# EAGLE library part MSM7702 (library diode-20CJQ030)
OKI's MSM7702-01/02/03 Single Rail CODEC Description: The MSM7702 is a single-channel CODEC CMOS IC for voice signals ranging from 300 to 3400 Hz with filters for A/D and D/A conversion. Designed especially for a single-power supply and low-power applications, the device is optimized for telephone terminals in digital wireless systems or ISDN systems. The MSM7702 utilizes low-voltage operational amplifiers (Op-amps) to provide low-power consumption. The device uses the same transmission clocks as those used in the MSM7508B and MSM7509B. The analog output signal can directly drive a piezoelectric type handset receiver. Features: Single power supply: +2.7 V to +3.8 V Low power consumption - Operating mode: 15 mW Typ. VDD = 3 V - Power save mode: 3.6 mW Typ. VDD = 3 V - Power down mode: 0.05 mW Typ. VDD = 3 V ITU-T Companding law - MSM7702-01: m/A-law pin selectable - MSM7702-02: m-law - MSM7702-03: A-law Built-in PLL eliminates a master clock Serial data rate: 64/128/256/512/1024/2048kHz 96/192/384/768/1536/1544/200 kHz Adjustable transmit gain Built-in reference voltage supply Analog output can directly drive a load equivalent to 1.2 kW Pin-for-pin compatible with the MSM7578 and MSM7579 Please send any comments to: messi@users.sourceforge.net
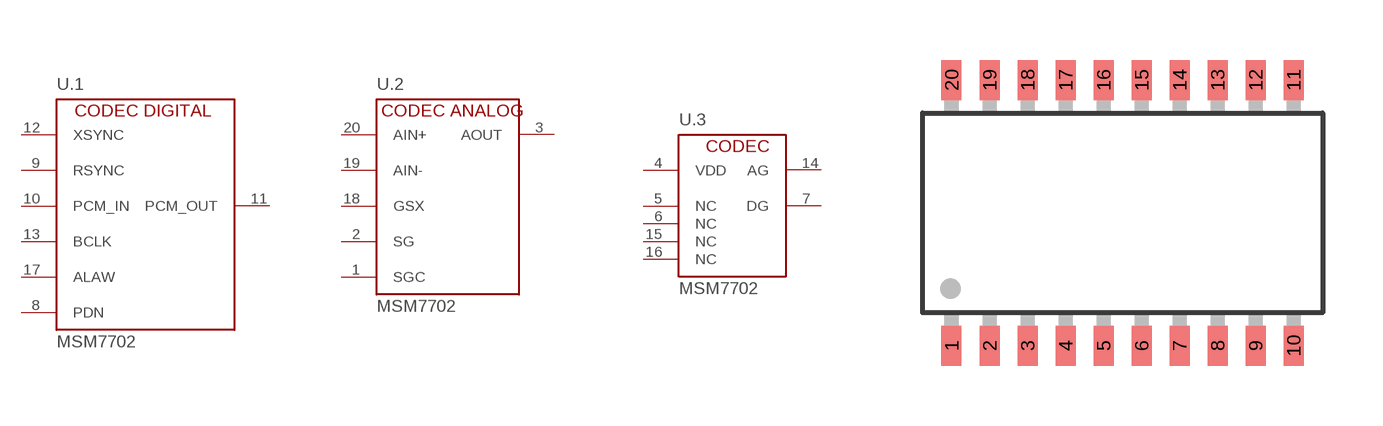
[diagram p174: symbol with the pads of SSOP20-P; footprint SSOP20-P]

Designator prefix U; gates .1=MSM7717_DIGITAL .2=MSM7702_ANALOG .3=MSM7702_PWR

## MSM7702-01  [SSOP20-P]
1  .2:SGC  in
2  .2:SG  in
3  .2:AOUT  out
4  .3:VDD  pwr
5  .3:NC  nc
6  .3:NC  nc
7  .3:DG  pwr
8  .1:PDN  in
9  .1:RSYNC  in
10  .1:PCM_IN  in
11  .1:PCM_OUT  out
12  .1:XSYNC  in
13  .1:BCLK  in
14  .3:AG  pwr
15  .3:NC  nc
16  .3:NC  nc
17  .1:ALAW  in
18  .2:GSX  in
19  .2:AIN-  in
20  .2:AIN+  in

## Footprint SSOP20-P (pad centres in mm)
SSOP20 package for the OKI 7702 and 7717
smd 0.5 x 1: 1 -4.275,-3.325; 2 -3.325,-3.325; 3 -2.375,-3.325; 4 -1.425,-3.325; 5 -0.475,-3.325; 6 0.475,-3.325; 7 1.425,-3.325; 8 2.375,-3.325; 9 3.325,-3.325; 10 4.275,-3.325; 11 4.275,3.325; 12 3.325,3.325; 13 2.375,3.325; 14 1.425,3.325; 15 0.475,3.325; 16 -0.475,3.325; 17 -1.425,3.325; 18 -2.375,3.325; 19 -3.325,3.325; 20 -4.275,3.325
